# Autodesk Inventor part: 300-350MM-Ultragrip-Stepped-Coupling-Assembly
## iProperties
Created: 2014-09
Part Number: 300-350MM-Ultragrip-Stepped-Coupling-Assembly
Document SubType Name: Modeling
Designer: raris
Density: 1 g/cm^3
Author: raris
